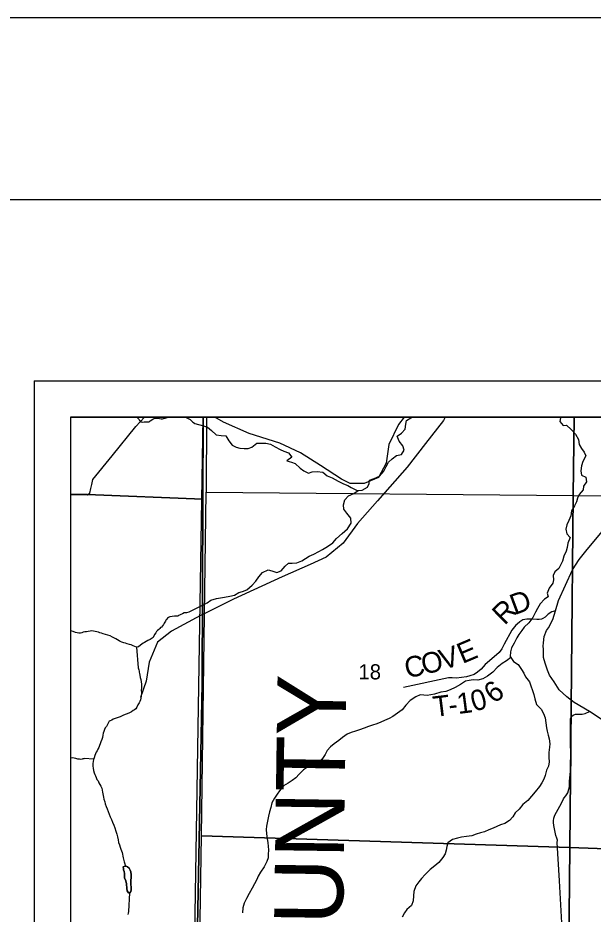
# Model space of a CAD drawing. Extents: x -1.2 to 34, y -8.5 to 22.
# Drawn here: x 1.955 to 3.539, y 19.531 to 22 of the extents above; entities that cross this region are included whole.
import ezdxf

# ---------------------------------------------------------------- set-up
doc = ezdxf.new("R2010")
doc.units = 0
for name, color, linetype in [('DV_X_County_Line', 7, 'Continuous'), ('GM_X_County_Text', 7, 'Continuous'), ('GM_X_Minor_Lake', 7, 'Continuous'), ('GM_X_Minor_River', 7, 'Continuous'), ('GM_X_Rail_Line', 7, 'Continuous'), ('GM_X_Section', 7, 'Continuous'), ('GM_X_Section_Text', 7, 'Continuous'), ('GM_X_Township_Road', 7, 'Continuous'), ('GM_X_Township_Road_Text', 7, 'Continuous'), ('GM_X_Unincorporated_Text', 7, 'Continuous'), ('SH_Border', 7, 'Continuous'), ('SH_Cut_Line', 7, 'Continuous'), ('SH_Data', 7, 'Continuous')]:
    doc.layers.add(name, color=color, linetype=linetype)

msp = doc.modelspace()

# ---------------------------------------------------------------- linework, layer by layer
at = {"layer": 'DV_X_County_Line'}
msp.add_line((2.3586, 14.1), (2.465, 20.9), dxfattribs=at)
at = {"layer": 'GM_X_Minor_Lake'}
for points in [[(2.2534, 19.6633), (2.2496, 19.6632), (2.2451, 19.6609), (2.2456, 19.6564), (2.2464, 19.6526), (2.248, 19.648), (2.2488, 19.6427), (2.2485, 19.6382), (2.249, 19.6306), (2.2521, 19.6223), (2.2541, 19.6147), (2.2554, 19.6018), (2.2562, 19.5948), (2.2594, 19.5893)], [(2.2594, 19.5893), (2.2562, 19.5948), (2.2554, 19.6018), (2.2541, 19.6147), (2.2521, 19.6223), (2.249, 19.6306), (2.2485, 19.6382), (2.2488, 19.6427), (2.248, 19.648), (2.2464, 19.6526), (2.2456, 19.6564), (2.2451, 19.6609), (2.2496, 19.6632), (2.2534, 19.6633), (2.2573, 19.6615), (2.2615, 19.6573), (2.2642, 19.6524), (2.2658, 19.6479), (2.2671, 19.6396), (2.2668, 19.6297), (2.2661, 19.6251), (2.2662, 19.6198), (2.2663, 19.6153), (2.2672, 19.6023), (2.2673, 19.5978), (2.2666, 19.5932), (2.2636, 19.5894), (2.2594, 19.5893)], [(2.2594, 19.5893), (2.2636, 19.5894), (2.2666, 19.5932), (2.2673, 19.5978), (2.2672, 19.6023), (2.2663, 19.6153), (2.2662, 19.6198), (2.2661, 19.6251), (2.2668, 19.6297), (2.2671, 19.6396), (2.2658, 19.6479), (2.2642, 19.6524), (2.2615, 19.6573), (2.2573, 19.6615), (2.2534, 19.6633)]]:
    msp.add_lwpolyline(points, dxfattribs=at)
at = {"layer": 'GM_X_Minor_River'}
for points in [[(2.284, 20.9), (2.2852, 20.8976), (2.2872, 20.8953), (2.2887, 20.8935), (2.2899, 20.8908), (2.2918, 20.8897), (2.2941, 20.8875), (2.2971, 20.8867), (2.3025, 20.8868), (2.3059, 20.8868), (2.3108, 20.8869), (2.3146, 20.887), (2.3165, 20.8874), (2.3191, 20.8897), (2.327, 20.8947), (2.3304, 20.8963), (2.3342, 20.8975), (2.3361, 20.8975), (2.3418, 20.8972), (2.3448, 20.8968), (2.3498, 20.8954), (2.3536, 20.8954), (2.3562, 20.8962), (2.3611, 20.8974), (2.3664, 20.899), (2.3695, 20.9)], [(2.4179, 20.9), (2.4184, 20.8996), (2.4238, 20.8967), (2.4276, 20.8948), (2.4299, 20.8933), (2.4314, 20.8915), (2.4341, 20.8892), (2.4364, 20.8873), (2.4391, 20.8855), (2.4426, 20.8829), (2.466, 20.876)], [(2.4646, 20.3817), (2.4764, 20.3887), (2.4865, 20.3957), (2.5016, 20.4004), (2.5129, 20.4024), (2.5243, 20.4041), (2.5386, 20.4069), (2.5514, 20.4101), (2.5638, 20.4171), (2.574, 20.4194), (2.5853, 20.4245), (2.5999, 20.4376), (2.6104, 20.4483), (2.6182, 20.4605), (2.629, 20.4721), (2.6441, 20.4798), (2.6543, 20.4765), (2.668, 20.4725), (2.6801, 20.4768), (2.6909, 20.4898), (2.7006, 20.4979), (2.7105, 20.4977), (2.7233, 20.4986), (2.7365, 20.5044), (2.7467, 20.511), (2.7572, 20.5172), (2.7704, 20.523), (2.7835, 20.5304), (2.794, 20.5354), (2.8079, 20.5439), (2.8218, 20.5543), (2.8323, 20.5658), (2.848, 20.5793), (2.8626, 20.592), (2.873, 20.6076), (2.8717, 20.622), (2.8606, 20.6356), (2.8529, 20.6469), (2.852, 20.659), (2.8553, 20.6723), (2.8654, 20.683), (2.8804, 20.6897), (2.8917, 20.6978), (2.9034, 20.6986), (2.9181, 20.7075), (2.9221, 20.7174), (2.9235, 20.7269), (2.9359, 20.7313), (2.9506, 20.7371), (2.963, 20.7513), (2.9689, 20.7643), (2.9752, 20.7765), (2.986, 20.7849), (2.9973, 20.7946), (3.0112, 20.797), (3.0183, 20.8096), (3.0147, 20.8213), (3.0044, 20.8337), (2.9993, 20.8473), (3.0109, 20.8558), (3.021, 20.8669), (3.0228, 20.881), (3.0249, 20.8908), (3.0369, 20.8978), (3.0429, 20.9)], [(3.449, 20.9), (3.4489, 20.8985), (3.4471, 20.8882), (3.4559, 20.8773), (3.4654, 20.8777), (3.478, 20.8661), (3.4903, 20.8533), (3.4984, 20.8389), (3.5004, 20.8249), (3.5066, 20.8136), (3.5143, 20.8038), (3.5189, 20.7932), (3.5103, 20.7784), (3.5063, 20.7662), (3.5049, 20.7525), (3.5065, 20.7404), (3.5187, 20.7348), (3.5207, 20.7219), (3.5125, 20.7101), (3.511, 20.7002), (3.5005, 20.6872), (3.4961, 20.6766), (3.4931, 20.6671), (3.4879, 20.656), (3.4789, 20.6423), (3.4771, 20.6282), (3.4715, 20.6153), (3.4667, 20.6039), (3.4634, 20.5913), (3.4665, 20.5788), (3.4757, 20.5683), (3.469, 20.5534), (3.4669, 20.5409), (3.4647, 20.5306), (3.4583, 20.5173), (3.4547, 20.5032), (3.444, 20.4834)], [(2.466, 20.8764), (2.4776, 20.8723), (2.4887, 20.8634), (2.5013, 20.8514), (2.5153, 20.8493), (2.5274, 20.849), (2.5359, 20.8351), (2.5455, 20.8231), (2.5562, 20.8175), (2.5664, 20.815), (2.5782, 20.814), (2.5891, 20.8141), (2.5993, 20.8172), (2.6132, 20.8284), (2.626, 20.8289), (2.6374, 20.8287), (2.651, 20.8254), (2.6636, 20.8184), (2.6773, 20.8113), (2.6876, 20.8065), (2.7005, 20.8017), (2.7097, 20.7897), (2.6959, 20.7797), (2.7088, 20.7757), (2.7183, 20.7723), (2.7324, 20.7596), (2.742, 20.7521), (2.7556, 20.7462), (2.7658, 20.7494), (2.7791, 20.7503), (2.7946, 20.7482), (2.8064, 20.7385), (2.8201, 20.733), (2.8373, 20.724), (2.8517, 20.7163), (2.8631, 20.7115), (2.8727, 20.7059), (2.8913, 20.6975)], [(3.444, 20.4834), (3.4335, 20.4738), (3.4291, 20.4643), (3.43, 20.4522), (3.4278, 20.4423), (3.4177, 20.4293), (3.4119, 20.4152), (3.415, 20.4054), (3.4052, 20.3984), (3.3933, 20.3858), (3.3859, 20.3732), (3.3799, 20.3625), (3.3725, 20.3483), (3.3617, 20.3338), (3.349, 20.3219), (3.3423, 20.312), (3.3345, 20.3016), (3.3285, 20.2921), (3.3215, 20.2772), (3.3141, 20.2642), (3.3112, 20.2539), (3.3106, 20.2403), (3.3191, 20.2267), (3.332, 20.2185), (3.3416, 20.2046), (3.3478, 20.1944), (3.3525, 20.1846), (3.3632, 20.1707), (3.3675, 20.1602), (3.3718, 20.1473), (3.3757, 20.1364), (3.3782, 20.1243), (3.3829, 20.1088), (3.3955, 20.0952), (3.4017, 20.0836), (3.4068, 20.0719), (3.4088, 20.0579), (3.4105, 20.0446), (3.4121, 20.0348), (3.4153, 20.0242), (3.418, 20.0136), (3.4197, 20.0003), (3.4183, 19.9908), (3.4166, 19.976), (3.4171, 19.9624), (3.418, 19.9502), (3.4155, 19.9388), (3.4107, 19.9274), (3.4063, 19.9133), (3.4027, 19.903), (3.3975, 19.8927), (3.3908, 19.8828), (3.3789, 19.8675), (3.3688, 19.856), (3.3587, 19.8437), (3.3456, 19.8326), (3.3348, 19.8199), (3.3239, 19.8099), (3.3176, 19.7989), (3.3086, 19.7889), (3.2955, 19.7804), (3.2838, 19.7765), (3.274, 19.7722), (3.2635, 19.7675), (3.2514, 19.7632), (3.2401, 19.7581), (3.2288, 19.7546), (3.2171, 19.751), (3.2047, 19.7471), (3.1899, 19.7447), (3.176, 19.7426), (3.1658, 19.7398), (3.1518, 19.7362), (3.1387, 19.727), (3.1361, 19.7175), (3.134, 19.7068), (3.1315, 19.6973), (3.1248, 19.6866), (3.1143, 19.6732), (3.1027, 19.664), (3.09, 19.654), (3.0765, 19.6402), (3.066, 19.629), (3.0593, 19.6195), (3.0507, 19.6091), (3.0453, 19.5935), (3.0443, 19.581), (3.0437, 19.5677), (3.0385, 19.5551), (3.0261, 19.5436), (3.0198, 19.5341), (3.0135, 19.5226)], [(2.4646, 20.3817), (2.4261, 20.3627), (2.419, 20.3611), (2.4133, 20.3607), (2.4087, 20.3583), (2.4035, 20.3564), (2.4001, 20.3548), (2.3974, 20.3533), (2.3952, 20.3521), (2.3864, 20.3516), (2.3804, 20.3511), (2.3739, 20.3503), (2.372, 20.3495), (2.3698, 20.3484), (2.3675, 20.3464), (2.3649, 20.3437), (2.3627, 20.341), (2.3612, 20.3384), (2.3597, 20.3349), (2.3582, 20.3323), (2.3564, 20.3288), (2.3534, 20.3254), (2.3504, 20.3219), (2.3478, 20.3204), (2.3459, 20.3181), (2.3429, 20.315), (2.3399, 20.3123), (2.3373, 20.3092), (2.3347, 20.3061), (2.3317, 20.3015), (2.3273, 20.2935), (2.3198, 20.2877), (2.313, 20.2846), (2.3088, 20.2823), (2.3035, 20.2795), (2.3002, 20.2772), (2.2968, 20.2749), (2.2926, 20.2718), (2.287, 20.2676), (2.2821, 20.266), (2.2775, 20.2682), (2.2725, 20.2704), (2.2672, 20.2726), (2.2623, 20.2741), (2.2565, 20.2755), (2.2516, 20.277), (2.2466, 20.2784), (2.2417, 20.2799), (2.2371, 20.2817), (2.2337, 20.284), (2.2298, 20.2866), (2.2245, 20.2896), (2.2161, 20.294), (2.2092, 20.2973), (2.1905, 20.3036), (2.1852, 20.305), (2.181, 20.3061), (2.1768, 20.3076), (2.1722, 20.309), (2.168, 20.3097), (2.1638, 20.3108), (2.1593, 20.3112), (2.154, 20.3107), (2.149, 20.3099), (2.1445, 20.3091), (2.14, 20.3083), (2.1354, 20.3078), (2.1312, 20.3062), (2.1278, 20.3054), (2.1256, 20.305), (2.1233, 20.305), (2.1187, 20.3057), (2.1142, 20.3072), (2.1077, 20.3094), (2.1, 20.3115)], [(2.2821, 20.266), (2.2863, 20.2098), (2.2871, 20.2068), (2.2879, 20.2041), (2.2887, 20.2007), (2.2895, 20.1973), (2.2903, 20.1939), (2.2911, 20.1894), (2.292, 20.1833), (2.2936, 20.1773), (2.2948, 20.1708), (2.2956, 20.1647), (2.2957, 20.1594), (2.2954, 20.153), (2.2951, 20.148), (2.2956, 20.1416), (2.2952, 20.137), (2.2949, 20.1317), (2.2939, 20.126), (2.2928, 20.1214), (2.2913, 20.1172), (2.2887, 20.113), (2.2854, 20.1073), (2.2824, 20.1015), (2.2799, 20.0966), (2.2761, 20.0942), (2.2731, 20.0919), (2.2682, 20.0881), (2.261, 20.0846), (2.2531, 20.0818), (2.2459, 20.0787), (2.2373, 20.0744), (2.2263, 20.0704), (2.218, 20.0681), (2.2135, 20.0657), (2.2093, 20.0634), (2.2067, 20.0626), (2.2052, 20.0588), (2.203, 20.055), (2.2011, 20.0519), (2.1989, 20.0481), (2.1959, 20.0442), (2.1937, 20.0397), (2.1923, 20.0343), (2.1904, 20.0294), (2.1894, 20.0236), (2.1879, 20.0179), (2.1861, 20.0118), (2.1839, 20.0054), (2.1781, 19.9897), (2.1755, 19.9851), (2.1733, 19.9809), (2.171, 19.9771), (2.1688, 19.9725), (2.167, 19.9683), (2.1652, 19.9618), (2.1634, 19.9565), (2.1623, 19.9515), (2.162, 19.9458), (2.1617, 19.939), (2.1622, 19.9329), (2.163, 19.9265), (2.165, 19.9204), (2.1669, 19.9159), (2.1689, 19.9117), (2.1709, 19.9072), (2.1728, 19.9019), (2.1759, 19.8978), (2.1783, 19.8929), (2.181, 19.8883), (2.1833, 19.8834), (2.1861, 19.8778), (2.1877, 19.8721), (2.1885, 19.8668), (2.1893, 19.8622), (2.1901, 19.8577), (2.191, 19.8528), (2.1922, 19.8478), (2.1942, 19.8406), (2.1958, 19.8346), (2.1981, 19.8278), (2.2009, 19.8214), (2.2036, 19.8138), (2.2068, 19.8066), (2.2095, 19.7987), (2.2127, 19.7915), (2.2162, 19.7843), (2.2193, 19.7764), (2.2221, 19.7688), (2.2249, 19.7594), (2.2273, 19.7514), (2.2293, 19.7439), (2.2309, 19.7359), (2.2325, 19.7287), (2.2349, 19.7219), (2.2369, 19.7158), (2.2388, 19.7102), (2.2408, 19.7053)], [(3.3121, 20.2379), (3.3001, 20.2288), (3.2881, 20.2211), (3.275, 20.2107), (3.2626, 20.1972), (3.2484, 20.1861), (3.2349, 20.1791), (3.2213, 20.1755), (3.2088, 20.1761), (3.1974, 20.1749), (3.1873, 20.1729), (3.1737, 20.164), (3.1591, 20.1555), (3.1451, 20.1488), (3.1331, 20.1445), (3.1191, 20.1421), (3.1018, 20.137), (3.0821, 20.1337), (3.0723, 20.134), (3.0628, 20.135), (3.0504, 20.1299), (3.0354, 20.1195), (3.023, 20.1068), (3.013, 20.0938), (3.0006, 20.085), (2.9875, 20.0753), (2.9773, 20.0695), (2.9649, 20.0644), (2.9547, 20.0594), (2.9434, 20.0551), (2.9313, 20.0515), (2.92, 20.0476), (2.9087, 20.0429), (2.8955, 20.0386), (2.885, 20.0347), (2.8725, 20.0315), (2.8616, 20.0272), (2.8489, 20.0172), (2.8391, 20.0091), (2.8256, 20.0002), (2.8159, 19.9918), (2.8062, 19.9814), (2.8014, 19.9707), (2.7921, 19.9566), (2.7823, 19.9485), (2.7687, 19.9453), (2.7552, 19.938), (2.7413, 19.9287), (2.7293, 19.9164), (2.7207, 19.9068), (2.7106, 19.8991), (2.699, 19.8922), (2.6866, 19.8841), (2.6757, 19.871), (2.6694, 19.8615), (2.662, 19.8504), (2.6546, 19.8374), (2.6517, 19.8249), (2.6477, 19.8131), (2.6448, 19.8005), (2.6427, 19.7872), (2.6398, 19.7735), (2.6391, 19.7637), (2.6397, 19.7519), (2.6417, 19.7394), (2.6437, 19.7277), (2.6446, 19.7182), (2.6451, 19.7068), (2.6445, 19.6962), (2.6438, 19.6863), (2.6409, 19.6757), (2.6328, 19.6615), (2.6231, 19.647), (2.6168, 19.6359), (2.6127, 19.6264), (2.5998, 19.6024), (2.5924, 19.5879), (2.585, 19.5741), (2.5779, 19.5611), (2.5747, 19.5482), (2.5733, 19.5349)], [(2.1639, 19.9579), (2.1386, 19.9596), (2.1364, 19.9588), (2.1345, 19.9584), (2.1318, 19.9576), (2.1284, 19.9572), (2.125, 19.9575), (2.1201, 19.9582), (2.1151, 19.9593), (2.1102, 19.9607), (2.1056, 19.9611), (2.1011, 19.9603), (2.1, 19.9599)], [(2.2408, 19.7053), (2.242, 19.7003), (2.2448, 19.6863), (2.2457, 19.6825), (2.2465, 19.6787), (2.2477, 19.6753), (2.2484, 19.6727), (2.2513, 19.6633)], [(2.2625, 19.5894), (2.2594, 19.538), (2.2587, 19.5334), (2.2584, 19.5296)]]:
    msp.add_lwpolyline(points, dxfattribs=at)
at = {"layer": 'GM_X_Rail_Line'}
for points in [[(3.1319, 20.9), (3.1272, 20.8912), (3.0772, 20.8274), (3.0266, 20.7621), (2.9448, 20.6697), (2.8906, 20.6074), (2.8507, 20.5527), (2.804, 20.5147), (2.76, 20.4943), (2.6832, 20.4601), (2.5484, 20.3988), (2.4662, 20.3578)], [(3.0188, 20.9), (3.0032, 20.8802), (2.9764, 20.8252), (2.9686, 20.7734), (2.9481, 20.7341), (2.9089, 20.7169), (2.8696, 20.7169), (2.8461, 20.7295), (2.788, 20.7672), (2.733, 20.8018), (2.6765, 20.8285), (2.5917, 20.8552), (2.5211, 20.8867), (2.4972, 20.9)], [(2.4662, 20.3578), (2.4581, 20.3541), (2.378, 20.3102), (2.3399, 20.2803), (2.3164, 20.2251), (2.3086, 20.1732), (2.2927, 20.1276)]]:
    msp.add_lwpolyline(points, dxfattribs=at)
at = {"layer": 'GM_X_Section'}
for points in [[(3.4869, 20.9), (2.4742, 20.9), (2.4734, 20.6935), (3.4838, 20.6845)], [(4.504, 20.9), (3.4869, 20.9), (3.4838, 20.6845), (4.4978, 20.6761)], [(2.4734, 20.6935), (3.4838, 20.6845), (3.4745, 19.7148), (2.4611, 19.7462)], [(3.4838, 20.6845), (4.4978, 20.6761), (4.4756, 19.6778), (3.4745, 19.7148)], [(2.4611, 19.7462), (3.4745, 19.7148), (3.4647, 18.6909), (2.4444, 18.7044)], [(3.4745, 19.7148), (4.4756, 19.6778), (4.4573, 18.6708), (3.4647, 18.6909)]]:
    msp.add_lwpolyline(points, close=True, dxfattribs=at)
at = {"layer": 'GM_X_Township_Road'}
msp.add_line((3.4653, 19.298), (3.4459, 19.6223), dxfattribs=at)
for points in [[(2.1561, 20.7037), (2.1585, 20.7143), (2.1614, 20.7284), (2.2144, 20.7934), (2.2798, 20.874), (2.3041, 20.9)], [(2.1, 20.6866), (2.1462, 20.6861), (2.153, 20.6903), (2.1561, 20.7037)], [(3.6365, 20.0182), (3.5287, 20.0888), (3.4864, 20.1138), (3.4666, 20.1293), (3.445, 20.1486), (3.4313, 20.1707), (3.4191, 20.1891), (3.4132, 20.2034), (3.4071, 20.2222), (3.4022, 20.2378), (3.4019, 20.2512), (3.4019, 20.2606), (3.4014, 20.2693), (3.4017, 20.2785), (3.4042, 20.2954), (3.4103, 20.3121), (3.4158, 20.3194), (3.4277, 20.3425), (3.4352, 20.3662), (3.4434, 20.3954), (3.482, 20.4798), (3.5002, 20.508), (3.5184, 20.531), (3.5731, 20.5963)], [(3.4352, 20.3662), (3.4253, 20.3639), (3.4151, 20.3573), (3.4067, 20.3495), (3.4006, 20.345), (3.3964, 20.3435), (3.3903, 20.343), (3.3839, 20.3429), (3.371, 20.3437), (3.3562, 20.3439), (3.3457, 20.3416), (3.3371, 20.3365), (3.3295, 20.3294), (3.3259, 20.3266), (3.3219, 20.3228), (3.3146, 20.3136), (3.2937, 20.2747), (3.2877, 20.2614), (3.2801, 20.2517), (3.2659, 20.2402), (3.2415, 20.2183), (3.2302, 20.2061), (3.2205, 20.1974), (3.2116, 20.1912), (3.1998, 20.187), (3.1906, 20.1843), (3.1628, 20.181), (3.1511, 20.1815), (3.1407, 20.1822), (3.0172, 20.1551)], [(3.4459, 19.6223), (3.4396, 19.7281), (3.4404, 19.735), (3.4384, 19.7404), (3.4362, 19.7476), (3.4304, 19.7747), (3.4301, 19.783), (3.4298, 19.7884), (3.4308, 19.7954), (3.4334, 19.8036), (3.4514, 19.8371), (3.4575, 19.8488), (3.459, 19.8515), (3.4638, 19.8573), (3.4693, 19.8654), (3.472, 19.8751), (3.4733, 19.8821), (3.4739, 19.8959), (3.4783, 19.9434), (3.4778, 19.9738), (3.4764, 20.0011), (3.4764, 20.0687), (3.4791, 20.0752), (3.4837, 20.0792), (3.4906, 20.0814), (3.4987, 20.0821), (3.5088, 20.0822), (3.5168, 20.0838), (3.5287, 20.0888)]]:
    msp.add_lwpolyline(points, dxfattribs=at)
at = {"layer": 'GM_X_Unincorporated_Text'}
for p, q in [((2.1, 20.6871), (2.1, 14.6393)), ((2.146, 20.6866), (2.1, 20.6871)), ((2.4644, 20.6742), (2.146, 20.6866)), ((2.4628, 20.1657), (2.4644, 20.6742)), ((2.4414, 19.0677), (2.4628, 20.1657))]:
    msp.add_line(p, q, dxfattribs=at)
msp.add_lwpolyline([(2.465, 20.9), (2.1, 20.9), (2.1, 20.6871), (2.146, 20.6866), (2.4644, 20.6742)], close=True, dxfattribs=at)
msp.add_lwpolyline([(8.4143, 20.9), (2.465, 20.9), (2.4644, 20.6742), (2.4628, 20.1657), (2.4414, 19.0677), (2.4258, 17.6899), (2.8968, 17.6806), (3.3984, 17.6707), (4.1759, 17.654), (4.4093, 17.6489), (4.6867, 17.6371)], dxfattribs=at)
at = {"layer": 'SH_Border'}
msp.add_lwpolyline([(1.5, 21.5), (33.5, 21.5), (33.5, 0.5), (1.5, 0.5)], close=True, dxfattribs=at)
at = {"layer": 'SH_Cut_Line'}
for points in [[(0, 0), (34, 0), (34, 22), (0, 22)], [(2.465, 20.9), (2.1, 20.9), (2.1, 14.1), (2.3586, 14.1), (2.3643, 14.4203), (2.3672, 14.6322), (2.3867, 15.3183), (2.402, 16.1209), (2.4189, 17.3824), (2.4258, 17.6899), (2.4414, 19.0677), (2.4628, 20.1657), (2.4644, 20.6742)]]:
    msp.add_lwpolyline(points, close=True, dxfattribs=at)
msp.add_lwpolyline([(8.9, 20.9), (2.465, 20.9), (2.4644, 20.6742), (2.4628, 20.1657), (2.4414, 19.0677), (2.4258, 17.6899), (2.8968, 17.6806), (3.3984, 17.6707), (4.1759, 17.654), (4.4093, 17.6489), (4.6867, 17.6371)], dxfattribs=at)
at = {"layer": 'SH_Data'}
for p, q in [((2, 21), (9, 21)), ((2, 21), (2, 14)), ((2, 21), (2, 14)), ((2.1, 20.9), (2.1, 14.1)), ((2.1, 20.9), (8.9, 20.9)), ((2.1, 20.9), (2.1, 14.1))]:
    msp.add_line(p, q, dxfattribs=at)

# ---------------------------------------------------------------- texts
at = {"layer": 'GM_X_County_Text'}
msp.add_text('CARROLL COUNTY', height=0.189394, rotation=89.1839, dxfattribs=at).set_placement((2.8263, 17.8542))
at = {"layer": 'GM_X_Section_Text'}
msp.add_text('18', height=0.04186, rotation=0, dxfattribs=at).set_placement((2.8927, 20.1776))
at = {"layer": 'GM_X_Township_Road_Text'}
for s, rotation, p in [('D', 20.5089, (3.3227, 20.3544)), ('R', 44.4632, (3.2947, 20.3251)), ('V', 17.3372, (3.1257, 20.2029)), ('E', 22.8819, (3.179, 20.2198)), ('O', 13.0546, (3.0725, 20.1904)), ('C', 12.3927, (3.0262, 20.1802)), ('6', 38.4032, (3.266, 20.1089)), ('0', 15.7077, (3.2106, 20.0883)), ('T', 7.0182, (3.1014, 20.0738)), ('1', 7.4988, (3.1672, 20.082)), ('-', 7.0981, (3.1436, 20.079))]:
    msp.add_text(s, height=0.0568, rotation=rotation, dxfattribs=at).set_placement(p)

doc.saveas('drawing.dxf')
